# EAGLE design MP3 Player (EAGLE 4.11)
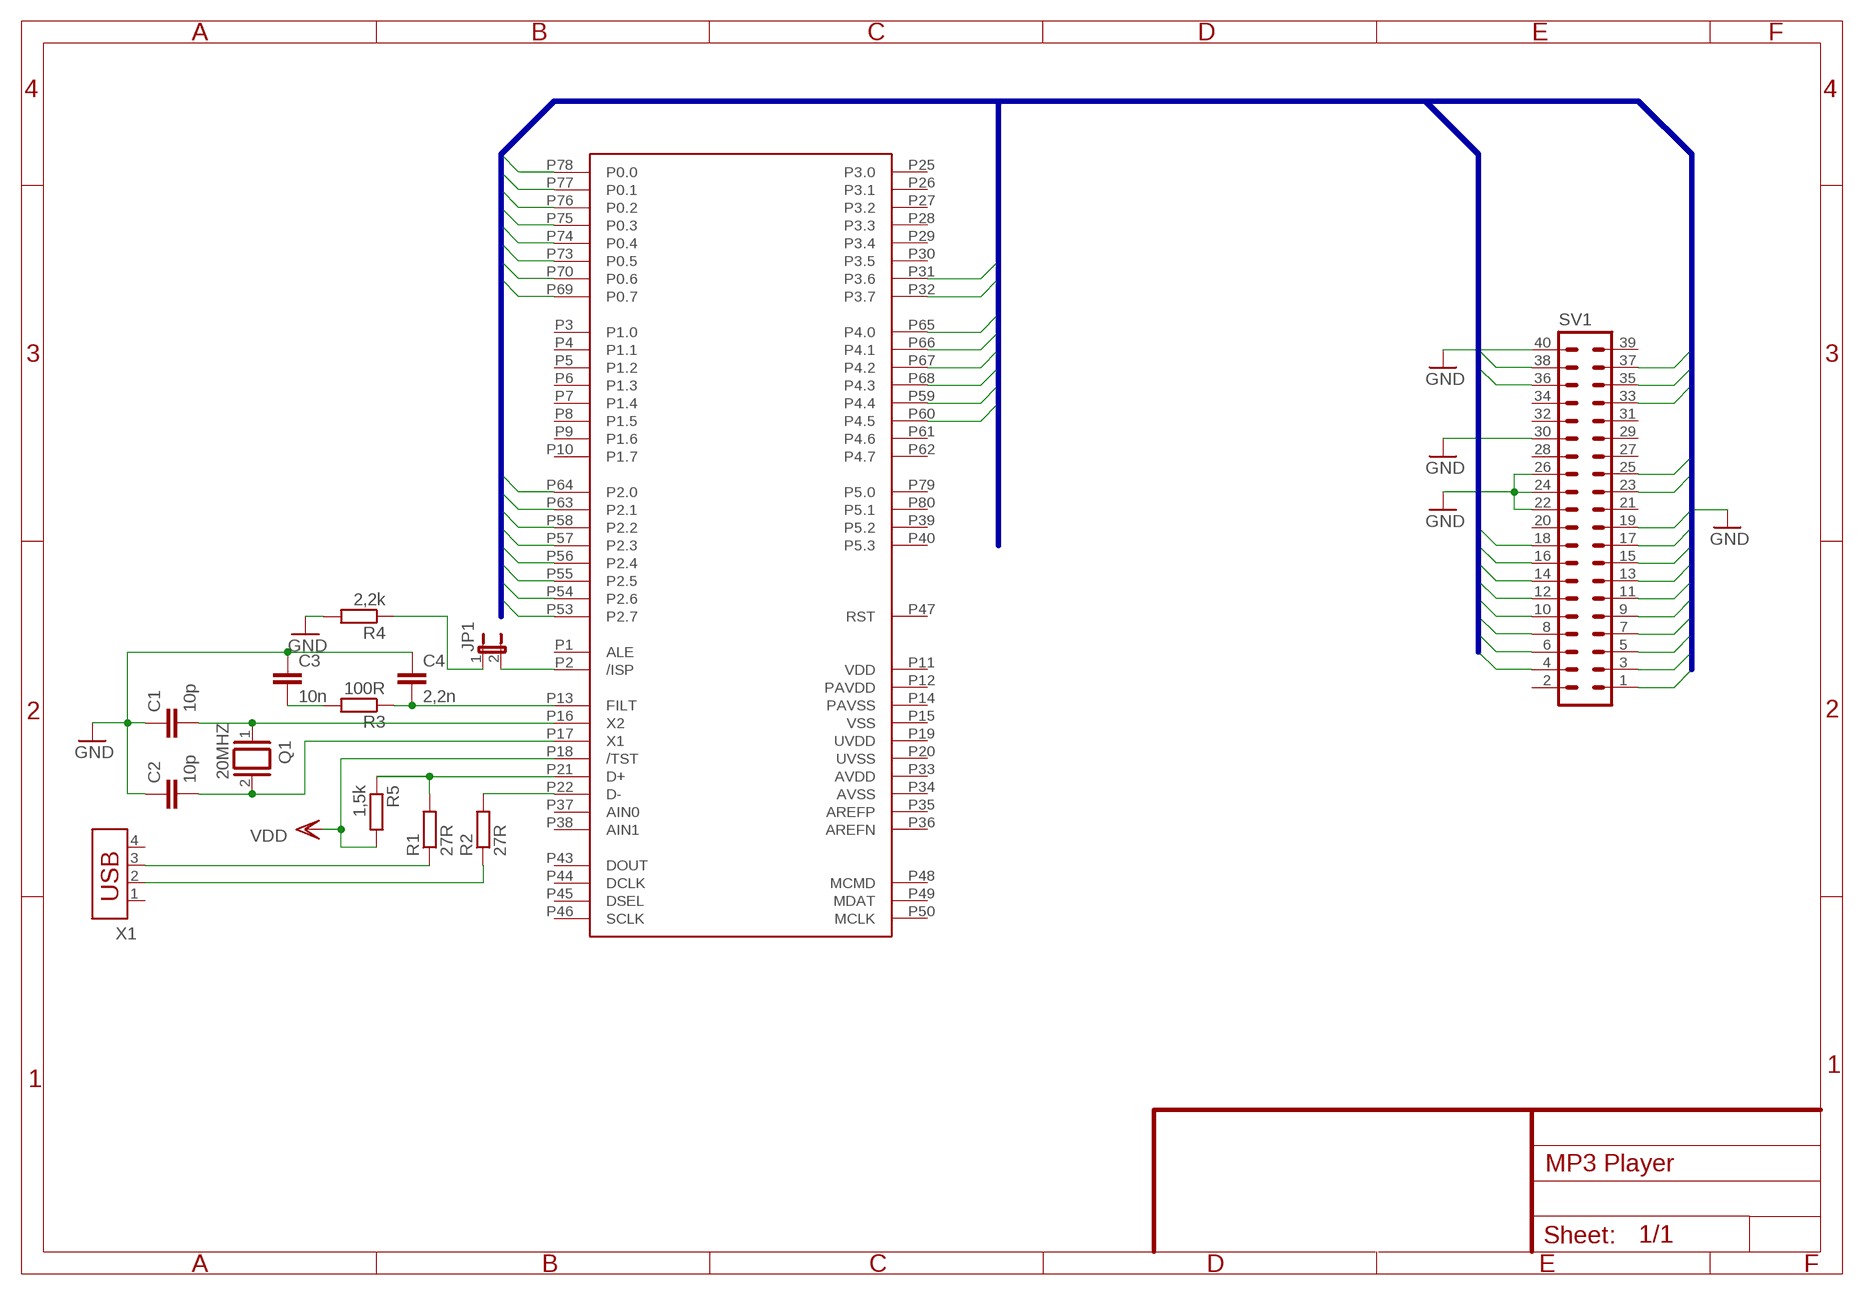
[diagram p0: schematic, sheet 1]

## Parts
C1  10p  C-EUC0805  [C0805]
C2  10p  C-EUC0805  [C0805]
C3  10n  C-EUC0805  [C0805]
C4  2,2n  C-EUC0805  [C0805]
JP1  JP1E  [JP1]
Q1  20MHZ  XTAL/S  [QS]
R1  27R  R-EU_M0805  [M0805]
R2  27R  R-EU_M0805  [M0805]
R3  100R  R-EU_M0805  [M0805]
R4  2,2k  R-EU_M0805  [M0805]
R5  1,5k  R-EU_M0805  [M0805]
SV1  ML40  [ML40]
U$1  AT89C51SND1C  [TQFP80]
X1  USB-787616  [USB]

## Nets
/ISP: JP1.1 R4.1
/ISP_UC: JP1.2 U$1.P2(/ISP)
/RD: SV1.25 U$1.P32(P3.7)
/WR: SV1.23 U$1.P31(P3.6)
A0: SV1.35 U$1.P65(P4.0)
A1: SV1.33 U$1.P66(P4.1)
A2: SV1.36 U$1.P67(P4.2)
CS0: SV1.37 U$1.P68(P4.3)
CS1: SV1.38 U$1.P59(P4.4)
D0: SV1.17 U$1.P78(P0.0)
D1: SV1.15 U$1.P77(P0.1)
D2: SV1.13 U$1.P76(P0.2)
D3: SV1.11 U$1.P75(P0.3)
D4: SV1.9 U$1.P74(P0.4)
D5: SV1.7 U$1.P73(P0.5)
D6: SV1.5 U$1.P70(P0.6)
D7: SV1.3 U$1.P69(P0.7)
D8: SV1.4 U$1.P64(P2.0)
D9: SV1.6 U$1.P63(P2.1)
D10: SV1.8 U$1.P58(P2.2)
D11: SV1.10 U$1.P57(P2.3)
D12: SV1.12 U$1.P56(P2.4)
D13: SV1.14 U$1.P55(P2.5)
D14: SV1.16 U$1.P54(P2.6)
D15: SV1.18 U$1.P53(P2.7)
D+: R1.1 X1.3
D+_UC: R1.2 R5.1 U$1.P21(D+)
D-: R2.1 X1.2
D-_UC: R2.2 U$1.P22(D-)
FILT: C3.2 R3.2
FILT_UC: C4.2 R3.1 U$1.P13(FILT)
GND: C1.1 C2.1 C3.1 C4.1 R4.2 SV1.19 SV1.22 SV1.24 SV1.26 SV1.30 SV1.40
RST_IDE: SV1.1 U$1.P60(P4.5)
VDD: R5.2 U$1.P18(/TST)
X1: C2.2 Q1.2 U$1.P17(X1)
X2: C1.2 Q1.1 U$1.P16(X2)
Unconnected: SV1.2 SV1.20 SV1.21 SV1.27 SV1.28 SV1.29 SV1.31 SV1.32 SV1.34 SV1.39 U$1.P1(ALE) U$1.P3(P1.0) U$1.P4(P1.1) U$1.P5(P1.2) U$1.P6(P1.3) U$1.P7(P1.4) U$1.P8(P1.5) U$1.P9(P1.6) U$1.P10(P1.7) U$1.P25(P3.0) U$1.P26(P3.1) U$1.P27(P3.2) U$1.P28(P3.3) U$1.P29(P3.4) U$1.P30(P3.5) U$1.P37(AIN0) U$1.P38(AIN1) U$1.P39(P5.2) U$1.P40(P5.3) U$1.P43(DOUT) U$1.P44(DCLK) U$1.P45(DSEL) U$1.P46(SCLK) U$1.P47(RST) U$1.P48(MCMD) U$1.P49(MDAT) U$1.P50(MCLK) U$1.P61(P4.6) U$1.P62(P4.7) U$1.P79(P5.0) U$1.P80(P5.1) X1.1 X1.4

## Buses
B$1

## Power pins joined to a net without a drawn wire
AREFN: U$1.P36(AREFN)
AREFP: U$1.P35(AREFP)
AVDD: U$1.P33(AVDD)
AVSS: U$1.P34(AVSS)
PAVDD: U$1.P12(PAVDD)
PAVSS: U$1.P14(PAVSS)
UVDD: U$1.P19(UVDD)
UVSS: U$1.P20(UVSS)
VDD: U$1.P11(VDD)
VSS: U$1.P15(VSS)

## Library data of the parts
C1-C4 = rcl:C-EU: CAPACITOR, European symbol
JP1 = jumper:JP1E: JUMPER
Q1 = special:XTAL/S: CRYSTAL
R1-R5 = rcl:R-EU_: RESISTOR, European symbol
SV1 = con-ml:ML40: HARTING
U$1 = mp3:AT89C51SND1C
X1 = con-amp:USB-787616: AMP connector

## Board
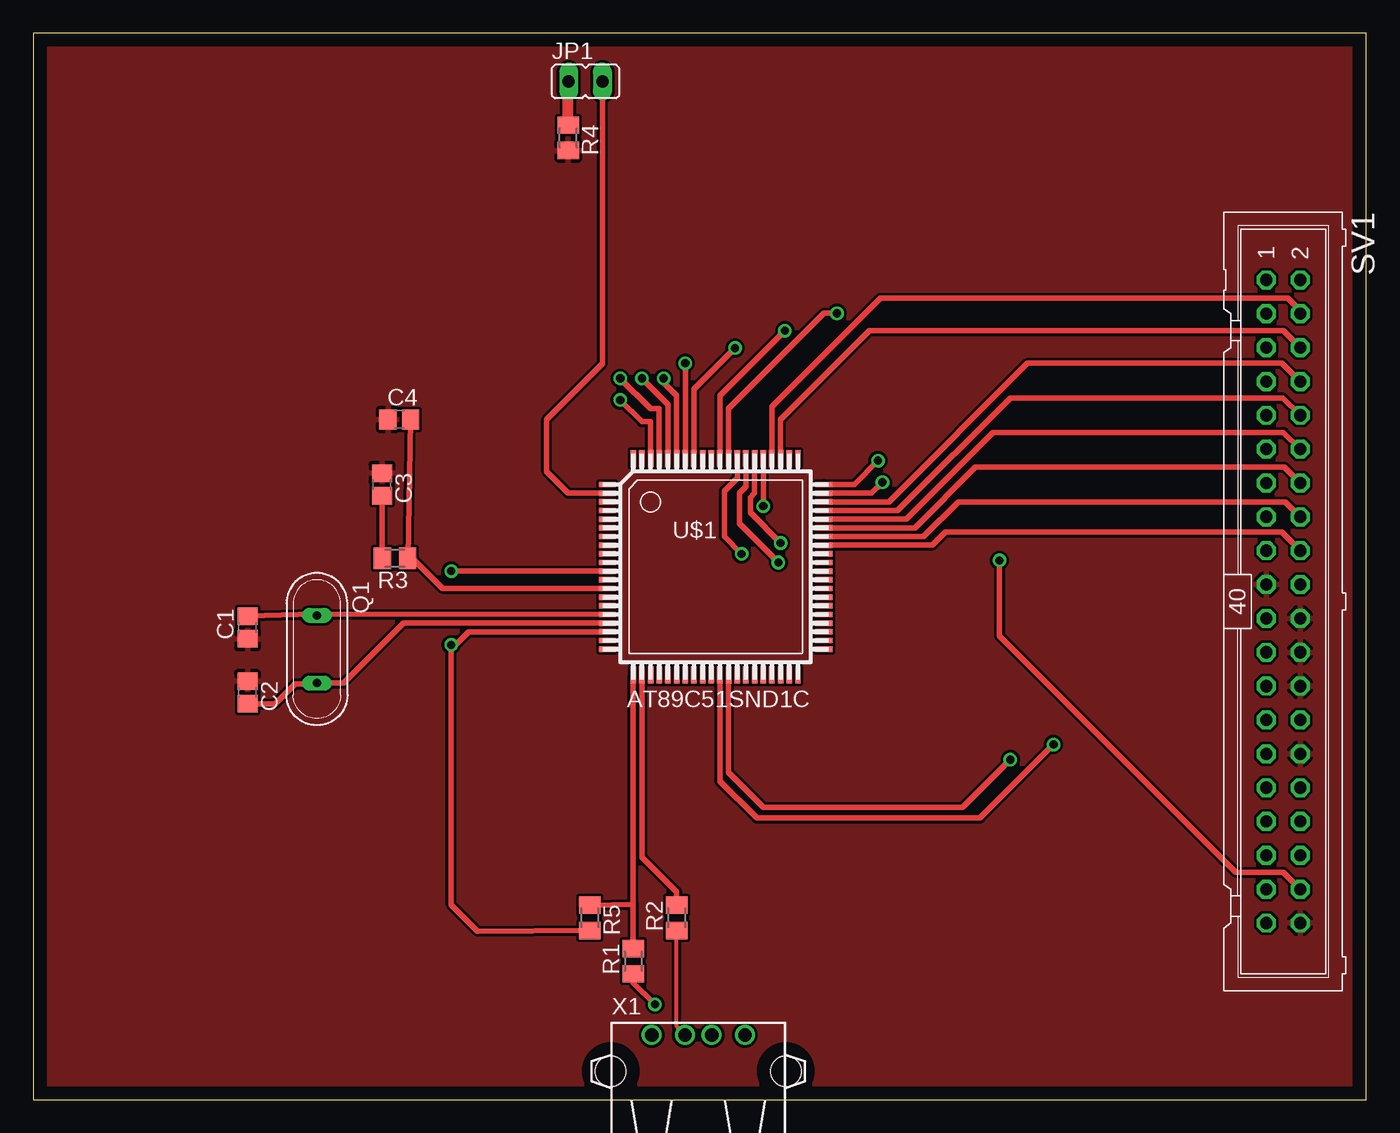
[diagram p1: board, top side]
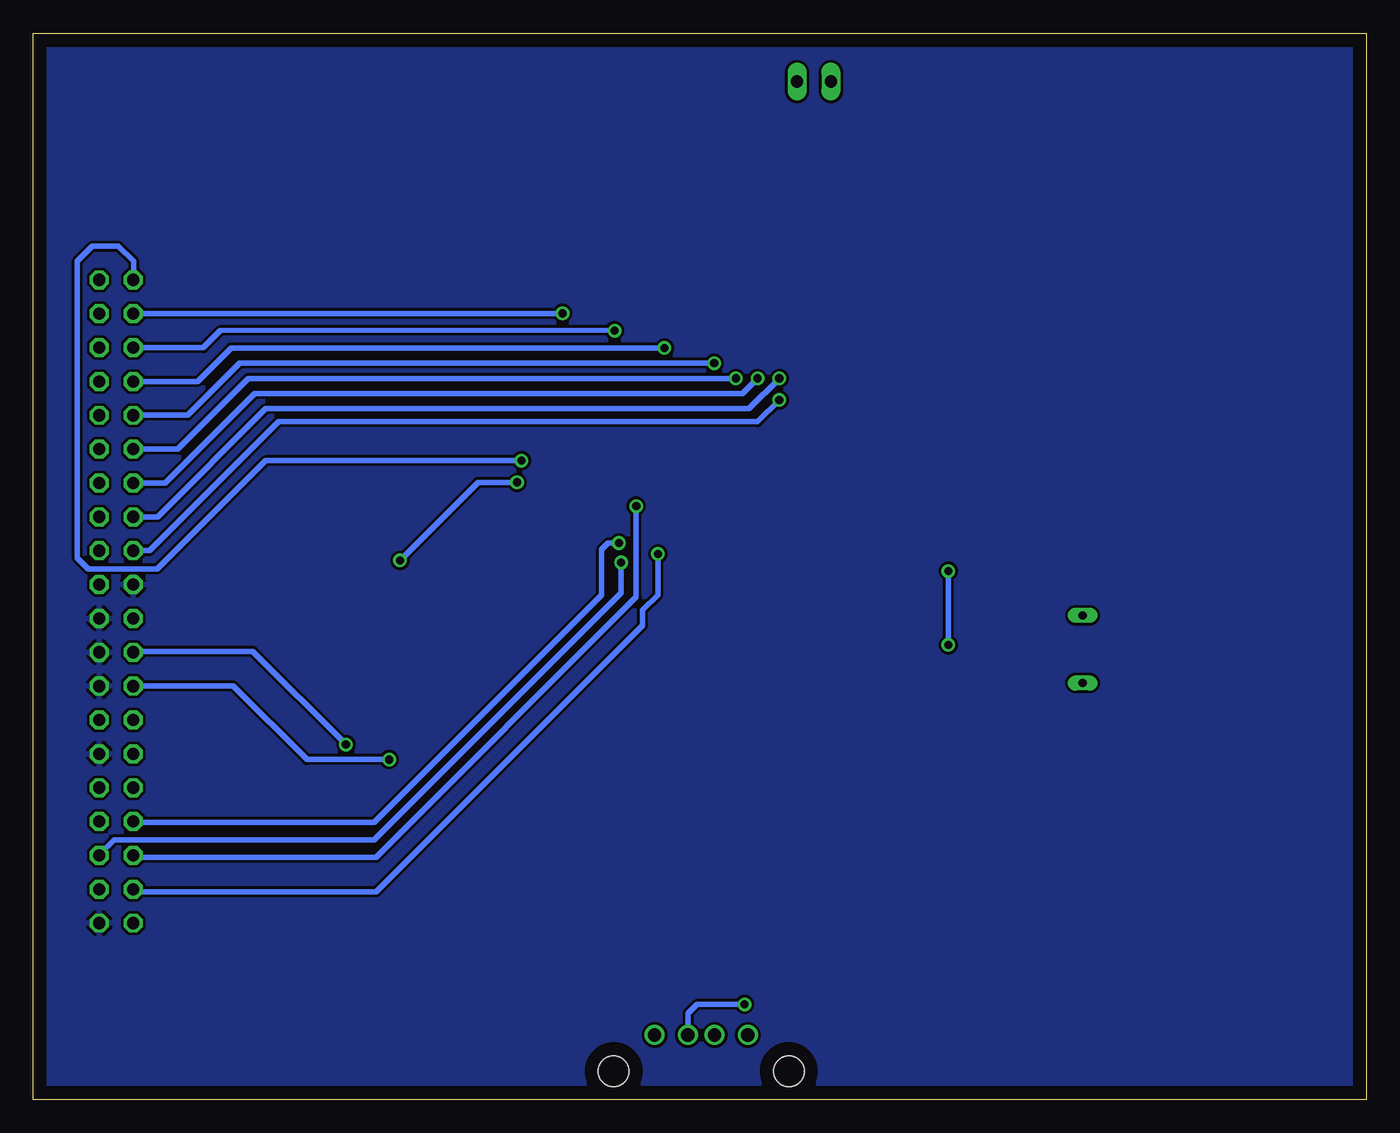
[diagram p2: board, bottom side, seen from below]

Size 100 x 80 mm. Coordinates in mm from the lower left corner, seen from the top.
Outline: 0,0 100,0 100,80 0,80 0,0
Copper layers (1*16): Top 0.035mm / dielectric 1.5mm / Bottom 0.035mm
Design rules "default": minimum track width 10mil, minimum drill 24mil, track to track 8mil, track to pad 8mil, pad to pad 8mil, via to via 10mil, smd to smd 8mil, copper to edge 40mil, drill to drill 8mil, minimum pad ring 10mil, minimum via ring 8mil, stop-mask expansion 4mil, vias tented up to drill 0mil, thermal gap 10mil

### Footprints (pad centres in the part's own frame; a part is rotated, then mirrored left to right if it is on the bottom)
C0805 = smd 1.3 x 1.5: 1 -0.85,0; 2 0.85,0
JP1 = drill 0.914 long: 1 0,-1.27; 2 0,1.27
QS = drill 0.61 long: 1 -2.54,0; 2 2.54,0
M0805 = smd 1.3 x 1.6: 1 -0.95,0; 2 0.95,0
ML40 = drill 0.914 octagon: 1 -24.13,-1.27; 2 -24.13,1.27; 3 -21.59,-1.27; 4 -21.59,1.27; 5 -19.05,-1.27; 6 -19.05,1.27; 7 -16.51,-1.27; 8 -16.51,1.27; 9 -13.97,-1.27; 10 -13.97,1.27; 11 -11.43,-1.27; 12 -11.43,1.27; 13 -8.89,-1.27; 14 -8.89,1.27; 15 -6.35,-1.27; 16 -6.35,1.27; 17 -3.81,-1.27; 18 -3.81,1.27; 19 -1.27,-1.27; 20 -1.27,1.27; 21 1.27,-1.27; 22 1.27,1.27; 23 3.81,-1.27; 24 3.81,1.27; 25 6.35,-1.27; 26 6.35,1.27; 27 8.89,-1.27; 28 8.89,1.27; 29 11.43,-1.27; 30 11.43,1.27; 31 13.97,-1.27; 32 13.97,1.27; 33 16.51,-1.27; 34 16.51,1.27; 35 19.05,-1.27; 36 19.05,1.27; 37 21.59,-1.27; 38 21.59,1.27; 39 24.13,-1.27; 40 24.13,1.27
TQFP80 = smd 1.27 x 0.406: P1 -8.128,6.177; P2 -8.128,5.527; P3 -8.128,4.877; P4 -8.128,4.227; P5 -8.128,3.576; P6 -8.128,2.926; P7 -8.128,2.276; P8 -8.128,1.626; P9 -8.128,0.975; P10 -8.128,0.325; P11 -8.128,-0.325; P12 -8.128,-0.975; P13 -8.128,-1.626; P14 -8.128,-2.276; P15 -8.128,-2.926; P16 -8.128,-3.576; P17 -8.128,-4.227; P18 -8.128,-4.877; P19 -8.128,-5.527; P20 -8.128,-6.177; P41 8.128,-6.177; P42 8.128,-5.527; P43 8.128,-4.877; P44 8.128,-4.227; P45 8.128,-3.576; P46 8.128,-2.926; P47 8.128,-2.276; P48 8.128,-1.626; P49 8.128,-0.975; P50 8.128,-0.325; P51 8.128,0.325; P52 8.128,0.975; P53 8.128,1.626; P54 8.128,2.276; P55 8.128,2.926; P56 8.128,3.576; P57 8.128,4.227; P58 8.128,4.877; P59 8.128,5.527; P60 8.128,6.177 | smd 0.406 x 1.27: P21 -6.177,-8.128; P22 -5.527,-8.128; P23 -4.877,-8.128; P24 -4.227,-8.128; P25 -3.576,-8.128; P26 -2.926,-8.128; P27 -2.276,-8.128; P28 -1.626,-8.128; P29 -0.975,-8.128; P30 -0.325,-8.128; P31 0.325,-8.128; P32 0.975,-8.128; P33 1.626,-8.128; P34 2.276,-8.128; P35 2.926,-8.128; P36 3.576,-8.128; P37 4.227,-8.128; P38 4.877,-8.128; P39 5.527,-8.128; P40 6.177,-8.128; P61 6.177,8.128; P62 5.527,8.128; P63 4.877,8.128; P64 4.227,8.128; P65 3.576,8.128; P66 2.926,8.128; P67 2.276,8.128; P68 1.626,8.128; P69 0.975,8.128; P70 0.325,8.128; P71 -0.325,8.128; P72 -0.975,8.128; P73 -1.625,8.128; P74 -2.276,8.128; P75 -2.926,8.128; P76 -3.576,8.128; P77 -4.226,8.128; P78 -4.877,8.128; P79 -5.527,8.128; P80 -6.177,8.128
USB = drill 1 round: 1 -3.5,12.99; 2 -1,12.99; 3 1,12.99; 4 3.5,12.99 | hole 2.3: -6.57,10.28; 6.57,10.28

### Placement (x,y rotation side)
C1  16.08,35.42 90 top
C2  16.08,30.54 270 top
C3  26.15,46.15 270 top
C4  27.45,51.02 0 top
JP1  41.44,76.38 270 top
Q1  21.28,33.79 270 top
R1  45.01,10.38 90 top
R2  48.26,13.63 90 top
R3  27.13,40.62 180 top
R4  40.13,72.16 270 top
R5  41.76,13.63 270 top
SV1  93.78,37.37 270 top
U$1  51.19,39.97 0 top
X1  49.89,-8.15 0 top

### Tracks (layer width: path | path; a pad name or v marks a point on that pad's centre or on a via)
/ISP
  Top 0.813: JP1.1 40.13,76.38 R4.1
/ISP_UC
  Top 0.406: JP1.2 42.7,55.22 38.51,51.02 38.51,47.12 40.13,45.5 42.74,45.5 U$1.P2
/RD  (via drill 0.61)
  Top 0.406: U$1.P32 52.16,24.53 54.77,21.93 69.72,21.93 v73.3,25.5
  Bottom 0.406: v73.3,25.5 79.47,25.5 85,31.03 92.48,31.03 92.49,31.02 SV1.25
/WR  (via drill 0.61)
  Top 0.406: U$1.P31 51.51,23.88 54.28,21.11 71.02,21.11 v76.55,26.64
  Bottom 0.406: 92.58,33.63 92.64,33.63 | 92.58,33.63 SV1.23 | v76.55,26.64 83.54,33.63 92.58,33.63
A0  (via drill 0.61)
  Top 0.406: v54.77,44.52 U$1.P65
  Bottom 0.406: v54.77,44.52 54.77,37.69 74.27,18.19 92.32,18.19 92.48,18.35 SV1.35
A1  (via drill 0.61)
  Top 0.406: U$1.P66 54.12,45.5 53.79,45.17 53.79,44.03 v56.07,41.76
  Bottom 0.406: 57.53,37.69 | 57.53,37.69 57.37,37.86 57.37,41.27 56.88,41.76 v56.07,41.76 | 57.53,37.69 74.44,20.79 92.48,20.79 92.51,20.82 SV1.33
A2  (via drill 0.61)
  Top 0.406: U$1.P67 53.46,45.98 52.98,45.5 52.98,43.22 v55.9,40.3
  Bottom 0.406: v55.9,40.3 55.9,38.02 74.44,19.49 93.94,19.49 95.08,18.35 SV1.36 | SV1.36
CS0  (via drill 0.61)
  Top 0.406: U$1.P68 52.81,46.63 51.84,45.66 51.84,42.25 v53.14,40.95
  Bottom 0.406: v53.14,40.95 53.14,37.86 54.28,36.72 54.28,35.58 74.27,15.59 92.48,15.59 92.51,15.62 SV1.37
CS1  (via drill 0.61)
  Top 0.406: U$1.P59 62.89,45.5 v63.71,46.31 | v72.48,40.46 72.48,34.77 90.2,17.05 93.78,17.05 SV1.38 95.08,15.75
  Bottom 0.406: v63.71,46.31 66.63,46.31 v72.48,40.46
D0  (via drill 0.61)
  Top 0.406: v44.04,52.49 45.66,50.86 46.31,50.86 U$1.P78
  Bottom 0.406: SV1.17 91.27,41.18 81.59,50.86 45.66,50.86 v44.04,52.49
D1  (via drill 0.61)
  Top 0.406: v44.04,54.11 46.31,51.84 46.96,51.84 U$1.P77
  Bottom 0.406: SV1.15 90.68,43.72 82.56,51.84 46.31,51.84 v44.04,54.11
D2  (via drill 0.61)
  Top 0.406: v45.66,54.11 47.61,52.16 U$1.P76
  Bottom 0.406: SV1.13 90.09,46.26 83.38,52.97 46.8,52.97 v45.66,54.11
D3  (via drill 0.61)
  Top 0.406: v47.29,54.11 47.29,53.79 48.26,52.81 48.26,48.26 | 48.26,48.26 | U$1.P75 48.26,48.26
  Bottom 0.406: SV1.11 89.18,48.8 83.86,54.11 v47.29,54.11
D4  (via drill 0.61)
  Top 0.406: U$1.P74 v48.91,55.25
  Bottom 0.406: SV1.9 88.42,51.34 84.51,55.25 48.92,55.24 v48.91,55.25
D5  (via drill 0.61)
  Top 0.406: U$1.P73 49.56,53.3 v52.65,56.39
  Bottom 0.406: SV1.7 87.67,53.88 85.16,56.39 v52.65,56.39 | v52.65,56.39 52.72,56.32 | v52.65,56.39 52.49,56.23 v52.65,56.39
D6  (via drill 0.61)
  Top 0.406: v56.39,57.69 51.51,52.81 U$1.P70 51.51,47.94
  Bottom 0.406: SV1.5 87.25,56.42 85.98,57.69 56.26,57.72 v56.39,57.69
D7  (via drill 0.61)
  Top 0.406: v60.29,58.99 59.32,58.99 52.16,51.84 U$1.P69
  Bottom 0.406: SV1.3 60.32,58.96 v60.29,58.99
D8
  Top 0.406: 95.05,58.86 SV1.4 95.05,59.18 94.11,60.13 63.54,60.13 55.41,52 U$1.P64
D9
  Top 0.406: SV1.6 93.78,57.69 62.73,57.69 56.07,51.02 U$1.P63
D10
  Top 0.406: SV1.8 93.68,55.25 74.6,55.25 64.19,44.85 U$1.P58
D11
  Top 0.406: SV1.10 93.74,52.65 73.3,52.65 64.84,44.2 U$1.P57
D12
  Top 0.406: SV1.12 93.8,50.05 72,50.05 65.49,43.55 U$1.P56
D13
  Top 0.406: SV1.14 93.86,47.45 70.7,47.45 66.14,42.9 U$1.P55
D14
  Top 0.406: SV1.16 93.92,44.85 69.39,44.85 66.8,42.25 U$1.P54 | U$1.P54
D15
  Top 0.406: SV1.18 93.66,42.57 68.42,42.57 67.44,41.6 U$1.P53
D+  (via drill 0.61)
  Top 0.406: R1.1 45.01,8.76 v46.64,7.13
  Bottom 0.406: v46.64,7.13 50.21,7.13 50.86,6.48 50.88,4.84 X1.3
D+_UC
  Top 0.406: 45,14.66 R1.2 | 45,14.66 U$1.P21 | R5.1 45,14.66
D-
  Top 0.305: X1.2 48.26,5.51 R2.1
D-_UC
  Top 0.406: R2.2 48.26,15.59 45.66,18.19 U$1.P22
FILT
  Top 0.406: R3.2 26.15,40.62 C3.2
FILT_UC
  Top 0.406: 28.11,40.62 28.43,40.62 30.71,38.34 U$1.P13 | R3.1 28.11,40.62 | 28.11,40.62 C4.2
GND
  Top 0.406: C4.1 26.15,51.02
  pour Top: 0.8,78.66 0.8,0.96 0.47,0.63 99.31,0.63 99.31,79.31 0.8,79.31 0.8,78.33
  pour Bottom: 0.8,79.31 0.8,0.63 99.31,0.63 99.31,79.31
RST_IDE  (via drill 0.61)
  Top 0.406: U$1.P60 61.59,46.15 v63.38,47.94
  Bottom 0.406: v63.38,47.94 82.56,47.94 90.69,39.81 95.89,39.81 96.71,40.62 96.71,62.89 95.57,64.03 93.62,64.03 92.48,62.89 92.48,61.59 92.51,61.56 SV1.1
VDD  (via drill 0.61)
  Top 0.406: v31.36,39.64 U$1.P11 | U$1.P18 32.66,35.09 31.68,34.12 v31.36,34.12 31.36,14.61 33.33,12.63 R5.2
  Bottom 0.406: v31.36,34.12 v31.36,39.64
X1
  Top 0.406: U$1.P17 | U$1.P17 27.78,35.74 23.29,31.25 Q1.2 21.28,31.19 19.65,31.19 18.15,29.69 C2.2
X2
  Top 0.406: 21.15,36.43 U$1.P16 | 21.15,36.43 Q1.1 | C1.2 21.15,36.43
